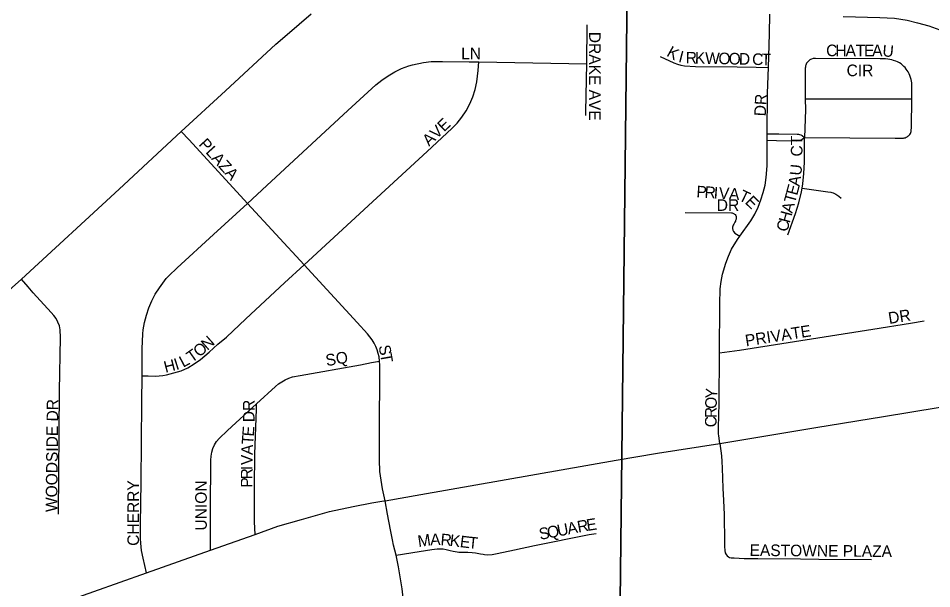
# Model space of a CAD drawing. Extents: x 1587405 to 1714697, y 1028970 to 1155083.
# Drawn here: x 1658990 to 1662922, y 1113561 to 1116017 of the extents above; entities that cross this region are included whole.
import ezdxf

# ---------------------------------------------------------------- set-up
doc = ezdxf.new("R2010")
doc.units = 0
for name, color, linetype in [('GM_X_City_Street', 7, 'Continuous'), ('GM_X_City_Street_Text', 7, 'Continuous'), ('GM_X_Section', 7, 'Continuous'), ('GM_X_State_Route', 7, 'Continuous'), ('GM_X_US_Route', 7, 'Continuous')]:
    doc.layers.add(name, color=color, linetype=linetype)

msp = doc.modelspace()

# ---------------------------------------------------------------- linework, layer by layer
at = {"layer": 'GM_X_City_Street'}
for points in [[(1662219.1, 1115805.3), (1662224, 1115950), (1662225.4, 1116034.1)], [(1662540.4, 1116024.6), (1662698.8, 1116019.6), (1662761.7, 1116017.7), (1662816.1, 1116009.3), (1662860.7, 1115996.8), (1662909.2, 1115984.1), (1662956.6, 1115967.6), (1663002.5, 1115947.5), (1663046.9, 1115924.4), (1663089.8, 1115898.7), (1663130.9, 1115869.9), (1663169.4, 1115837.7), (1663200, 1115807.9)], [(1661436.5, 1115821.1), (1661439.2, 1115989.2)], [(1659977.4, 1115218.8), (1660059.5, 1115297.1), (1660408.9, 1115619.5), (1660529.6, 1115730.4), (1660555.1, 1115750.9), (1660582.2, 1115769.4), (1660610.5, 1115785.9), (1660640, 1115800.3), (1660670.4, 1115812.3), (1660686.2, 1115816.7), (1660734.4, 1115826.3), (1660767, 1115830.2), (1660816.1, 1115831.4), (1660930.4, 1115829.8), (1660973, 1115829.1)], [(1660220.2, 1114955.3), (1660533.5, 1115243.5), (1660749.5, 1115442.9), (1660855.9, 1115541.9), (1660878.9, 1115565.7), (1660899.7, 1115591.5), (1660918.4, 1115618.9), (1660934.3, 1115648), (1660947, 1115678.7), (1660956.7, 1115710.4), (1660963.4, 1115742.9), (1660968.9, 1115792), (1660973, 1115829.1)], [(1660973, 1115829.1), (1661436.5, 1115821.1)], [(1661753.3, 1115852.8), (1661812.3, 1115824.8), (1661826.8, 1115818.7), (1661841.7, 1115814.5), (1661857.1, 1115812.3), (1661905.4, 1115809.5), (1662084.1, 1115807.9), (1662165.5, 1115806.3), (1662219.1, 1115805.3)], [(1662836.1, 1115669.8), (1662835.9, 1115719.5), (1662836, 1115729.6), (1662835.3, 1115738.2), (1662834, 1115745.9), (1662832.4, 1115753.2), (1662830, 1115761.8), (1662827.3, 1115770.5), (1662824.4, 1115777.2), (1662819.9, 1115785.9), (1662816.3, 1115791.6), (1662812, 1115798.1), (1662807.3, 1115804.5), (1662802.2, 1115809.8), (1662795.4, 1115815.5), (1662789.4, 1115820.4), (1662782.5, 1115824.8), (1662774.9, 1115828.6), (1662767, 1115832), (1662757.7, 1115835.7), (1662750.1, 1115837.8), (1662741.3, 1115839.6), (1662732.9, 1115840.9), (1662723.2, 1115841.7), (1662712.1, 1115842.2), (1662700.2, 1115842.5), (1662420.6, 1115844), (1662411.9, 1115842.9), (1662404.5, 1115840.9), (1662400.5, 1115839.1), (1662397.3, 1115837.5), (1662390.5, 1115832.3), (1662386.2, 1115827.2), (1662383.2, 1115822.8), (1662381.5, 1115818.9), (1662379.9, 1115815.5), (1662378.8, 1115811.4), (1662377.8, 1115806.3), (1662377.5, 1115802.2), (1662377.5, 1115797.3), (1662377.4, 1115770), (1662377.5, 1115669.3)], [(1661432.6, 1115598.8), (1661433.2, 1115615.1), (1661436.5, 1115821.1)], [(1662213.8, 1115519.2), (1662215.2, 1115693.7), (1662219.1, 1115805.3)], [(1662374.6, 1115503.9), (1662569.3, 1115502.6), (1662764.8, 1115500.4), (1662784.4, 1115500), (1662796, 1115500.4), (1662799.7, 1115500.9), (1662803.2, 1115501.7), (1662807.3, 1115502.6), (1662811.4, 1115504.4), (1662815.8, 1115507), (1662818.6, 1115508.9), (1662821.3, 1115510.7), (1662824, 1115513.4), (1662827.1, 1115517), (1662829.8, 1115520.3), (1662831.7, 1115524.4), (1662832.8, 1115528.6), (1662833.5, 1115532.7), (1662834.8, 1115548.6), (1662836.1, 1115669.8)], [(1662377.5, 1115669.3), (1662377.6, 1115621.9), (1662374.6, 1115503.9)], [(1662377.5, 1115669.3), (1662414.9, 1115669.3), (1662609.2, 1115669.5), (1662819.8, 1115669.8), (1662836.1, 1115669.8)], [(1659977.4, 1115218.8), (1659725.1, 1115492.8), (1659691.8, 1115528.9)], [(1662213.5, 1115491.4), (1662213.8, 1115519.2)], [(1662213.8, 1115519.2), (1662262.8, 1115518.8), (1662341.9, 1115518.2), (1662348.3, 1115517.6), (1662351.8, 1115517), (1662358.2, 1115515.1), (1662363.8, 1115512), (1662374.6, 1115503.9)], [(1662096, 1115078.2), (1662142.8, 1115145), (1662159.7, 1115173.6), (1662174.2, 1115203.5), (1662186.5, 1115234.4), (1662196.6, 1115266.1), (1662204.3, 1115298.5), (1662209.2, 1115331.4), (1662212.6, 1115381.1), (1662213.5, 1115491.4)], [(1662213.5, 1115491.4), (1662253.3, 1115490.7), (1662341.4, 1115489.3), (1662348.5, 1115489.9), (1662351.3, 1115490.4), (1662355.4, 1115491.5), (1662359.6, 1115493.4), (1662363.3, 1115495.8), (1662374.6, 1115503.9)], [(1662364, 1115285.3), (1662366.9, 1115303.3), (1662371.6, 1115348.7), (1662373.7, 1115396.9), (1662374.6, 1115503.9)], [(1662302.7, 1115085), (1662335, 1115176), (1662349.7, 1115222), (1662361.2, 1115268.9), (1662364, 1115285.3)], [(1662364, 1115285.3), (1662474.7, 1115269.9), (1662487, 1115268.2), (1662492.3, 1115267), (1662496.7, 1115265.6), (1662503.6, 1115262.6), (1662508.7, 1115259.9), (1662521.8, 1115250.7), (1662531.5, 1115242.2)], [(1659523.3, 1114476.9), (1659523.9, 1114544), (1659523.6, 1114593.2), (1659525.7, 1114658.7), (1659527.7, 1114675), (1659533.5, 1114707.2), (1659541.3, 1114739), (1659551.6, 1114770.1), (1659564.5, 1114800.3), (1659579.7, 1114829.3), (1659597.5, 1114856.8), (1659627, 1114896.1), (1659637.9, 1114908.3), (1659673.6, 1114941.8), (1659830.3, 1115086.3), (1659977.4, 1115218.8)], [(1660220.2, 1114955.3), (1659977.4, 1115218.8)], [(1661860.6, 1115180.8), (1662059.8, 1115178.9), (1662063, 1115178.6), (1662066.1, 1115177.7), (1662068.5, 1115176.6), (1662071.2, 1115175.1), (1662073.2, 1115173.7), (1662075.6, 1115171.3), (1662078, 1115167.7), (1662079.7, 1115163), (1662080.2, 1115158.7), (1662080.2, 1115155.2), (1662079.8, 1115152.5), (1662078.7, 1115149.1), (1662077.6, 1115145.8), (1662076.3, 1115142.8), (1662074.3, 1115139.1), (1662069.4, 1115130.6), (1662067, 1115125.6), (1662064.6, 1115117.8), (1662064.3, 1115114.4), (1662064.3, 1115110.2), (1662065, 1115106.9), (1662065.9, 1115103.8), (1662067, 1115101.3), (1662068.5, 1115098.6), (1662074.2, 1115091.8), (1662096, 1115078.2)], [(1662007.6, 1114576.2), (1662009.1, 1114786.4), (1662011.4, 1114851.7), (1662015.1, 1114883.9), (1662021.4, 1114915.7), (1662035.1, 1114962.7), (1662046.6, 1114993.1), (1662060.4, 1115022.4), (1662085.9, 1115063.9), (1662096, 1115078.2)], [(1659523.3, 1114476.9), (1659548.8, 1114476.7), (1659580.5, 1114476.3), (1659611.9, 1114479), (1659628.1, 1114481.9), (1659660.2, 1114489.6), (1659690.9, 1114499.4), (1659719.4, 1114512.4), (1659747.5, 1114528.9), (1659774.6, 1114548), (1659812.4, 1114579.7), (1659849.6, 1114613.1), (1659886.4, 1114643.6), (1659969.6, 1114723.4), (1660136, 1114877.8), (1660220.2, 1114955.3)], [(1660544.3, 1114540.3), (1660542.7, 1114558.5), (1660539.4, 1114574.1), (1660534.7, 1114589.4), (1660528.6, 1114604.2), (1660521.3, 1114618.5), (1660512.8, 1114632.2), (1660493.3, 1114657.7), (1660449.4, 1114706.3), (1660220.2, 1114955.3)], [(1659163, 1113882.2), (1659168.1, 1114412.3), (1659171.3, 1114642.4), (1659170.6, 1114675.9), (1659167.4, 1114692.8), (1659161.1, 1114708.9), (1659152.8, 1114723.8), (1659143, 1114737.5), (1659132.4, 1114750.5), (1659054.1, 1114835.1), (1659033.2, 1114859.8), (1659004, 1114894.2)], [(1662007.6, 1114576.2), (1662094.2, 1114588.2), (1662667.6, 1114678.6), (1662829.5, 1114704.7), (1662889, 1114713.6)], [(1662009.2, 1114186.5), (1662005.2, 1114219.2), (1662004.5, 1114227.9), (1662003.5, 1114255.3), (1662006.1, 1114358.6), (1662007.6, 1114576.2)], [(1660016, 1114357.4), (1660097.1, 1114431.7), (1660110, 1114442.3), (1660123.8, 1114452.1), (1660138.5, 1114460.5), (1660154.2, 1114467.2), (1660170.3, 1114472.3), (1660202.9, 1114479.3), (1660462.5, 1114525), (1660511, 1114534.1), (1660544.3, 1114540.3)], [(1660568.6, 1113939.8), (1660558, 1113990.1), (1660546.3, 1114065.5), (1660544.1, 1114115.1), (1660544.9, 1114263.3), (1660546.4, 1114477.2), (1660546, 1114523.5), (1660544.3, 1114540.3)], [(1659541.7, 1113629.4), (1659527.6, 1113692.9), (1659520.5, 1113724.7), (1659518.4, 1113740.9), (1659516.3, 1113773.6), (1659516.4, 1113839.2), (1659519.2, 1114019.5), (1659522.3, 1114363.7), (1659523.3, 1114476.9)], [(1659817.4, 1113726.9), (1659817.5, 1113768.9), (1659817.6, 1113900.7), (1659819.4, 1114114.8), (1659820.5, 1114131.2), (1659823.3, 1114148), (1659827.9, 1114164.4), (1659834.7, 1114180.1), (1659843.7, 1114194.7), (1659854.5, 1114207.9), (1659890.5, 1114242.4), (1660016, 1114357.4)], [(1660009.1, 1113794.7), (1660006.9, 1113849.2), (1660007.1, 1113999.2), (1660008.8, 1114140.3), (1660015.2, 1114334.5), (1660016, 1114357.4)], [(1662009.2, 1114186.5), (1662016.6, 1114132.4), (1662017.9, 1114108.3), (1662019.8, 1114079.5), (1662022.6, 1113994), (1662025.5, 1113940.2), (1662027.7, 1113880), (1662028.2, 1113844.7), (1662029.4, 1113795.2), (1662029.8, 1113742.9), (1662030.6, 1113725.8), (1662033.1, 1113715.1), (1662036.2, 1113708.2), (1662041, 1113702), (1662047.2, 1113697.3), (1662050.6, 1113695.8), (1662057.9, 1113693.8), (1662071.8, 1113693.1), (1662114.4, 1113691.5), (1662173.7, 1113690.9), (1662357.4, 1113689.7), (1662436.3, 1113688.5), (1662662.5, 1113686.8)], [(1660615.9, 1113705.2), (1660605.5, 1113748.1), (1660600.1, 1113771.3), (1660591.8, 1113814.5), (1660579.7, 1113882), (1660568.6, 1113939.8)], [(1660615.9, 1113705.2), (1660715.1, 1113721.1), (1660770.3, 1113730.2), (1660793.1, 1113732.4), (1660803.4, 1113732.9), (1660809.5, 1113733), (1660819.2, 1113732.2), (1660831.9, 1113729), (1660849.4, 1113724.7), (1660861.9, 1113721.8), (1660879, 1113719.3), (1660886.2, 1113718.5), (1660904.7, 1113718.1), (1660925.6, 1113717.8), (1660943.6, 1113716.4), (1660958.1, 1113715.2), (1660979.4, 1113711.6), (1660990.8, 1113709), (1660996.6, 1113707.5), (1661009.7, 1113706.8), (1661029.3, 1113708.2), (1661051.9, 1113712.3), (1661125.9, 1113727.5), (1661211.7, 1113747.4), (1661446.7, 1113793.5), (1661476.7, 1113799)], [(1660646.1, 1113192.2), (1660653.6, 1113316.4), (1660655, 1113365.3), (1660653.9, 1113414), (1660653, 1113444.4), (1660652.1, 1113464.8), (1660650.1, 1113494.7), (1660645.5, 1113535), (1660642.2, 1113559.8), (1660626.2, 1113655.3), (1660615.9, 1113705.2)]]:
    msp.add_lwpolyline(points, dxfattribs=at)
at = {"layer": 'GM_X_Section'}
for points in [[(1656263, 1118717.5), (1661639.2, 1118644.5), (1661579.6, 1113384), (1656195.7, 1113439)], [(1661639.2, 1118644.5), (1667042.5, 1118475.3), (1666972.8, 1113204.7), (1661579.6, 1113384)]]:
    msp.add_lwpolyline(points, close=True, dxfattribs=at)
at = {"layer": 'GM_X_State_Route'}
msp.add_lwpolyline([(1656575, 1112579.7), (1656620.2, 1112627.5), (1656664.8, 1112676.4), (1656911.6, 1112922.1), (1657015, 1113027.6), (1657329.2, 1113340.2), (1657506.5, 1113511.2), (1657662.8, 1113655.9), (1657795.9, 1113778), (1657979.6, 1113946.4), (1658050.1, 1114011), (1658302.9, 1114245.4), (1658530.1, 1114457.2), (1658682.5, 1114597.8), (1658880.3, 1114780.2), (1658903.1, 1114802.5), (1658924.1, 1114822.4), (1659004, 1114894.2), (1659423.8, 1115281.1), (1659691.8, 1115528.9), (1659882, 1115704.8), (1660099.2, 1115905.5), (1660146.8, 1115947.6), (1660250.7, 1116036.2)], dxfattribs=at)
at = {"layer": 'GM_X_US_Route'}
for points in [[(1660563.4, 1113938.9), (1660568.6, 1113939.8), (1660722.5, 1113965.9), (1661563.4, 1114114.4), (1661741.5, 1114143.9), (1662009.2, 1114186.5), (1662422.2, 1114255.1), (1662713.9, 1114302.3), (1663183.9, 1114379.3), (1663397.8, 1114413.4)], [(1656575, 1112579.7), (1656787, 1112653.2), (1656848.6, 1112676.2), (1657189, 1112795.7), (1658047.6, 1113099.8), (1658156.4, 1113138.9), (1658364.3, 1113212.3), (1658585.4, 1113289.9), (1658701.9, 1113334), (1659052.8, 1113456.4), (1659202.2, 1113509.2), (1659541.7, 1113629.4), (1659817.4, 1113726.9), (1660009.1, 1113794.7), (1660107.3, 1113829.5), (1660209.1, 1113859.4), (1660329.8, 1113892.8), (1660431.4, 1113914.5), (1660512.1, 1113930.2), (1660563.4, 1113938.9)]]:
    msp.add_lwpolyline(points, dxfattribs=at)

# ---------------------------------------------------------------- texts
at = {"layer": 'GM_X_City_Street_Text'}
for s, rotation, p in [('DRAKE AVE', 270, (1661447, 1115958.5)), ('C', 359.9028, (1662467.1, 1115853.5)), ('H', 359.9138, (1662506.7, 1115853.4)), ('A', 359.9126, (1662550.7, 1115853.4)), ('T', 359.918, (1662594.7, 1115853.3)), ('E', 359.918, (1662629.9, 1115853.2)), ('A', 359.9126, (1662665.1, 1115853.2)), ('U', 355.2509, (1662708, 1115853.2)), ('LN', 0, (1660896.4, 1115840.3)), ('K', 330.6292, (1661776.9, 1115856.5)), ('I', 345.4856, (1661828.3, 1115829.6)), ('R', 358.9255, (1661862.3, 1115822.4)), ('K', 358.7105, (1661901.8, 1115821.6)), ('W', 358.7238, (1661945.8, 1115820.6)), ('O', 358.7105, (1662003, 1115819.4)), ('O', 358.7092, (1662047, 1115818.4)), ('D', 358.7105, (1662091, 1115817.4)), ('C', 358.7233, (1662148.2, 1115816.1)), ('T', 358.716, (1662187.8, 1115815.2)), ('CIR', 0, (1662555.2, 1115767.5)), ('DR', 86.989, (1662207, 1115593.8)), ('AVE', 43.6036, (1660757.9, 1115463.7)), ('CT', 90, (1662365.3, 1115421.7)), ('PLAZA', 312.2717, (1659763.7, 1115472)), ('U', 84.5189, (1662359.8, 1115337.8)), ('A', 80.9453, (1662352.4, 1115291)), ('P', 356.2277, (1661907.5, 1115246.3)), ('R', 356.2356, (1661942.6, 1115244)), ('I', 356.1946, (1661982.1, 1115241.4)), ('V', 356.2432, (1662004.1, 1115239.9)), ('A', 356.2165, (1662048, 1115237)), ('T', 334.2536, (1662087.1, 1115235.4)), ('E', 74.9331, (1662342.1, 1115251.4)), ('DR', 0, (1661996.4, 1115187.6)), ('E', 315, (1662115.2, 1115222.7)), ('T', 74.8838, (1662332.9, 1115217.3)), ('A', 74.9104, (1662321.4, 1115174.9)), ('H', 74.8982, (1662310, 1115132.4)), ('C', 74.9153, (1662299.7, 1115094.2)), ('DR', 8.9673, (1662738.5, 1114700.6)), ('PRIVATE', 8.8195, (1662122.5, 1114603.8)), ('N', 41.751, (1659803.9, 1114584.6)), ('O', 40.1101, (1659769, 1114555.2)), ('S', 281.5778, (1660540.3, 1114605.4)), ('T', 35.0547, (1659736.4, 1114532.1)), ('SQ', 9.4564, (1660317.2, 1114518.7)), ('T', 279.5252, (1660547.3, 1114571.3)), ('H', 14.0627, (1659623.6, 1114489.9)), ('I', 17.9787, (1659669.8, 1114501.6)), ('L', 27.88, (1659699.5, 1114512)), ('Y', 86.7195, (1661997, 1114378.1)), ('WOODSIDE DR', 89.4097, (1659157.7, 1113890.6)), ('DR', 90, (1660007, 1114277.7)), ('O', 88.3821, (1661995.8, 1114334.5)), ('R', 89.9466, (1661995.8, 1114295.3)), ('C', 89.9514, (1661995.7, 1114255.7)), ('E', 85.7606, (1660003.6, 1114214.9)), ('T', 85.7898, (1660001, 1114179.8)), ('A', 86.785, (1659998.6, 1114136.1)), ('V', 89.5409, (1659998.2, 1114092.8)), ('I', 89.9573, (1659998.2, 1114070.9)), ('R', 89.9514, (1659998.2, 1114031.3)), ('CHERRY', 90, (1659509.8, 1113745.3)), ('UNION', 90, (1659801.5, 1113811.3)), ('P', 89.9727, (1659998.2, 1113996.1)), ('R', 10.5003, (1661400.5, 1113802.1)), ('E', 8.8874, (1661439.1, 1113809.2)), ('S', 10.8277, (1661236.4, 1113770.7)), ('Q', 10.817, (1661271, 1113777.3)), ('U', 10.8338, (1661314.2, 1113785.5)), ('A', 10.817, (1661357.4, 1113793.8)), ('M', 8.465, (1660713, 1113739.9)), ('A', 1.1366, (1660763.5, 1113747.5)), ('R', 355.6981, (1660806.2, 1113748.4)), ('K', 353.0105, (1660845.1, 1113745.5)), ('E', 352.9868, (1660888.8, 1113740.2)), ('T', 354.4529, (1660925.1, 1113735.7)), ('EASTOWNE PLAZA', 359.5416, (1662137.4, 1113701.9))]:
    msp.add_text(s, height=50, rotation=rotation, dxfattribs=at).set_placement(p)

doc.saveas('drawing.dxf')
